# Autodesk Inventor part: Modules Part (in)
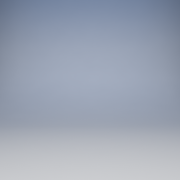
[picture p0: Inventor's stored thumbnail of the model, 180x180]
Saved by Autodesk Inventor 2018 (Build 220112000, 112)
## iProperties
Created: 2014-08
Part Number: Modules Part (in)
Material: Generic
Document SubType Name: Modeling
Designer: Wally
Manufacturer: Standard
Standards Organization: Custom
Density: 1 g/cm^3
Appearance: Default
Author: Wally
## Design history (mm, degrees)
node "Sketch1"
